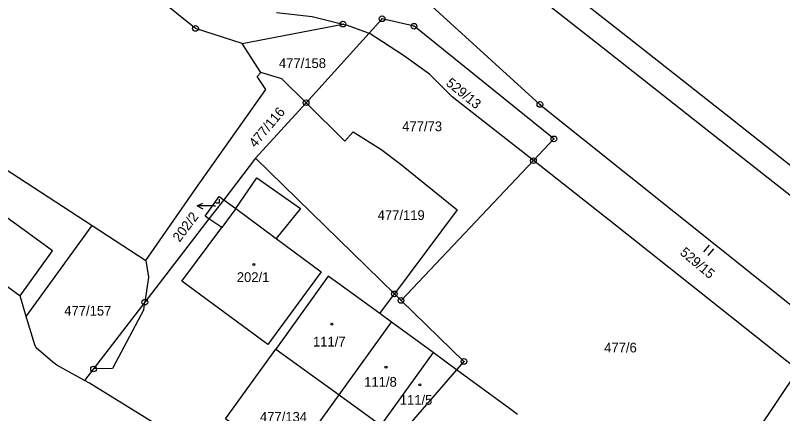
# Model space of a CAD drawing. Extents: x -758582 to -751794, y -998770 to -994350.
# Drawn here: x -754039.5 to -753905.6, y -997002.2 to -996932.8 of the extents above; entities that cross this region are included whole.
import ezdxf

# ---------------------------------------------------------------- set-up
doc = ezdxf.new("R2010")
doc.units = 0
for name, color, linetype in [('Hranice parcel', 7, 'Continuous'), ('Parcelní čísla', 7, 'Continuous'), ('Pop  PČ popisy', 7, 'Continuous'), ('Poz předměty', 7, 'Continuous'), ('Vnitřní kresba', 7, 'Continuous'), ('Značky bodu BP', 7, 'Continuous'), ('Značky budov', 7, 'Continuous'), ('Značky kultur', 7, 'Continuous')]:
    doc.layers.add(name, color=color, linetype=linetype)

msp = doc.modelspace()

# ---------------------------------------------------------------- linework, layer by layer
at = {"layer": 'Hranice parcel'}
for p, q in [((-753999.9, -996937.71), (-753982.32, -996934.32)), ((-753977.77, -996935.9), (-753988.76, -996948.02)), ((-753996.63, -996942.74), (-753999.9, -996937.71)), ((-754097.57, -996938.81), (-754038.66, -996981.68)), ((-753997.56, -996957.72), (-753988.76, -996948.02)), ((-753997.56, -996957.72), (-754003.12, -996964.95)), ((-753973.35, -996981.37), (-753997.56, -996957.72)), ((-753949.09, -996958.13), (-753972.19, -996982.5)), ((-754003.12, -996964.95), (-754005.69, -996968.29)), ((-754005.69, -996968.29), (-754016.88, -996982.83)), ((-754037.56, -996985.3), (-754026.08, -996969.43)), ((-754026.08, -996969.43), (-754016.73, -996975.52)), ((-754037.56, -996985.3), (-754038.66, -996981.68)), ((-753972.19, -996982.5), (-753973.35, -996981.37)), ((-753983, -996998.99), (-753973.86, -996986.29)), ((-753966.6, -996991.61), (-753973.86, -996986.29)), ((-753994.05, -996990.99), (-753983, -996998.99)), ((-753966.6, -996991.61), (-753975.71, -997004.26)), ((-753962.49, -996994.61), (-753966.6, -996991.61)), ((-753962.49, -996994.61), (-753972.77, -997006.39)), ((-753919.98, -997019.96), (-753902.88, -996994.67)), ((-753991.77, -997011.16), (-753983, -996998.99)), ((-753983, -996998.99), (-753975.71, -997004.26))]:
    msp.add_line(p, q, dxfattribs=at)
for points in [[(-753999.9, -996937.71), (-754008.04, -996935.07), (-754060.31, -996893.07), (-754081.1, -996876.57)], [(-753981.5, -996919.39), (-753974.47, -996924.94), (-753973.88, -996924.71), (-753947.95, -996948.33), (-753893.44, -996991.85), (-753859.56, -997018.21), (-753827.58, -997043.6)], [(-754114.92, -996922.81), (-754095.87, -996924.57), (-754049.13, -996954.42), (-754026.08, -996969.43)], [(-754038.66, -996981.68), (-754033.01, -996973.87), (-754092.2, -996930.79), (-754097.89, -996938.57), (-754097.57, -996938.81)], [(-753993.9, -996932.31), (-753987.69, -996932.98), (-753982.32, -996934.32)], [(-753949.09, -996958.13), (-753945.51, -996954.35), (-753969.92, -996934.7), (-753975.49, -996933.39), (-753977.77, -996935.9)], [(-753982.32, -996934.32), (-753981.75, -996934.46), (-753977.77, -996935.9)], [(-753949.09, -996958.13), (-753963.26, -996946.98), (-753967.22, -996943.04), (-753971.77, -996939.78), (-753977.77, -996935.9)], [(-754016.73, -996975.52), (-754008, -996963), (-753995.8, -996945.74), (-753997.29, -996943.45), (-753996.63, -996942.74)], [(-753988.76, -996948.02), (-753992.98, -996943.84), (-753996.63, -996942.74)], [(-753988.76, -996948.02), (-753981.98, -996954.75), (-753980.51, -996953.09), (-753975.72, -996956.1), (-753972.37, -996958.61), (-753962.37, -996966.69), (-753973.35, -996981.37)], [(-753902.88, -996994.67), (-753934.79, -996969.38), (-753949.09, -996958.13)], [(-754003.12, -996964.95), (-754000.98, -996966.5), (-753997.33, -996961.11), (-753989.73, -996966.45), (-753993.96, -996971.71), (-753986.11, -996977.53), (-753995.4, -996990.16), (-754010.41, -996979.12), (-754003.42, -996969.77), (-754005.69, -996968.29)], [(-754005.69, -996968.29), (-754006.38, -996967.83), (-754003.9, -996964.38), (-754003.12, -996964.95)], [(-754016.73, -996975.52), (-754016.27, -996978.44), (-754016.88, -996982.83)], [(-753973.86, -996986.29), (-753975.91, -996984.79), (-753983.27, -996979.45), (-753984.89, -996978.27), (-753994.05, -996990.99)], [(-754016.88, -996982.83), (-754025.83, -996994.46), (-754027.38, -996996.48)], [(-753972.19, -996982.5), (-753961.2, -996993.13), (-753962.49, -996994.61)], [(-754027.38, -996996.48), (-754032.26, -996993.8), (-754032.91, -996993.26), (-754035.82, -996990.75), (-754036.07, -996990.25), (-754037.56, -996985.3)], [(-753991.77, -997011.16), (-754002.82, -997003.16), (-753994.05, -996990.99)], [(-753951.85, -997002.38), (-753953.25, -997001.36), (-753962.49, -996994.61)], [(-754015.73, -997003.63), (-754026.51, -996996.96), (-754027.38, -996996.48)]]:
    msp.add_lwpolyline(points, dxfattribs=at)
at = {"layer": 'Pop  PČ popisy'}
for p, q in [((-754007.77, -996966.02), (-754006.77, -996965.52)), ((-754004.77, -996966.02), (-754007.77, -996966.02)), ((-754007.77, -996966.02), (-754006.77, -996966.52)), ((-754004.77, -996966.02), (-754004.55, -996966.02))]:
    msp.add_line(p, q, dxfattribs=at)
at = {"layer": 'Poz předměty'}
for p, q in [((-753934.3, -996935.34), (-753961.4, -996913.98)), ((-753936.92, -996938.52), (-753964.01, -996917.19)), ((-753915.46, -996950.17), (-753934.3, -996935.34)), ((-753918.17, -996953.29), (-753936.92, -996938.52)), ((-753883.37, -996975.43), (-753915.46, -996950.17)), ((-753885.72, -996978.83), (-753918.17, -996953.29))]:
    msp.add_line(p, q, dxfattribs=at)
at = {"layer": 'Vnitřní kresba'}
for p, q in [((-754000.98, -996966.5), (-754003.42, -996969.77)), ((-754000.98, -996966.5), (-753993.96, -996971.71)), ((-753975.91, -996984.79), (-753973.35, -996981.37)), ((-754017.05, -996984.1), (-754016.88, -996982.83)), ((-754017.05, -996984.1), (-754022.54, -996994.37)), ((-754022.54, -996994.37), (-754025.83, -996994.46))]:
    msp.add_line(p, q, dxfattribs=at)
at = {"layer": 'Značky bodu BP'}
for centre, radius in [((-753975.49, -996933.39), 0.5), ((-753975.49, -996933.39), 0.0303), ((-754008.04, -996935.07), 0.5), ((-754008.04, -996935.07), 0.0303), ((-753982.32, -996934.32), 0.5), ((-753982.32, -996934.32), 0.0303), ((-753969.92, -996934.7), 0.5), ((-753969.92, -996934.7), 0.0303), ((-753988.76, -996948.02), 0.5), ((-753988.76, -996948.02), 0.0303), ((-753947.95, -996948.33), 0.5), ((-753947.95, -996948.33), 0.0303), ((-753945.51, -996954.35), 0.5), ((-753945.51, -996954.35), 0.0303), ((-753949.09, -996958.13), 0.5), ((-753949.09, -996958.13), 0.0303), ((-753973.35, -996981.37), 0.5), ((-753973.35, -996981.37), 0.0303), ((-754016.88, -996982.83), 0.5), ((-754016.88, -996982.83), 0.0303), ((-753972.19, -996982.5), 0.5), ((-753972.19, -996982.5), 0.0303), ((-753961.2, -996993.13), 0.5), ((-754025.83, -996994.46), 0.5), ((-753961.2, -996993.13), 0.0303), ((-754025.83, -996994.46), 0.0303)]:
    msp.add_circle(centre, radius, dxfattribs=at)
at = {"layer": 'Značky budov'}
for centre in [(-753997.88, -996976.24), (-753984.26, -996986.64), (-753974.81, -996994.16), (-753968.92, -996997.21)]:
    msp.add_circle(centre, 0.175, dxfattribs=at)
at = {"layer": 'Značky kultur'}
for p, q in [((-754004.5, -996965.49), (-754003.83, -996965.49)), ((-754003.83, -996965.49), (-754003.83, -996964.82)), ((-753919.35, -996974.02), (-753918.39, -996972.87)), ((-753918.58, -996974.67), (-753917.62, -996973.52))]:
    msp.add_line(p, q, dxfattribs=at)

# ---------------------------------------------------------------- texts
at = {"layer": 'Parcelní čísla'}
for s, p in [('477/158', (-753993.49, -996941.98)), ('477/73', (-753971.98, -996952.99)), ('477/119', (-753976.27, -996968.48)), ('202/1', (-754000.84, -996979.29)), ('477/157', (-754030.94, -996985.15)), ('111/7', (-753987.55, -996990.54)), ('477/6', (-753936.74, -996991.57)), ('111/8', (-753978.61, -996997.55)), ('111/5', (-753972.41, -997000.7)), ('477/134', (-753996.8, -997003.65))]:
    msp.add_text(s, height=1.7, dxfattribs=at).set_placement(p)
for s, rotation, p in [('529/13', 321, (-753964.49, -996944.85)), ('477/116', 50, (-753997.59, -996955.99)), ('202/2', 53, (-754010.83, -996972.46)), ('529/15', 320, (-753923.66, -996974.37))]:
    msp.add_text(s, height=1.7, rotation=rotation, dxfattribs=at).set_placement(p)

doc.saveas('drawing.dxf')
